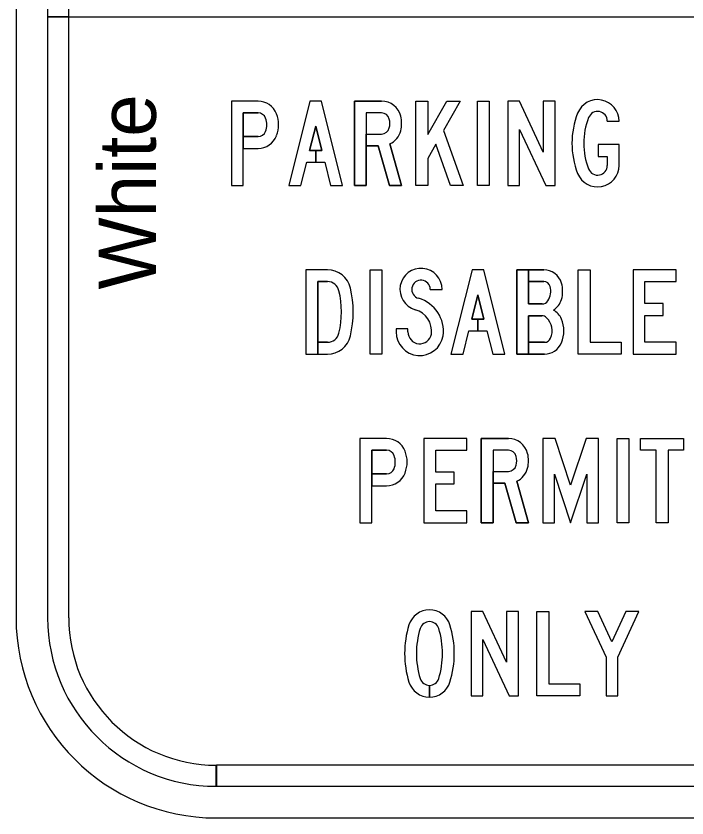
# Model space of a CAD drawing. Extents: x 0 to 770, y 0 to 495.
# Drawn here: x 274.24 to 315.4, y 369.75 to 418.91 of the extents above; entities that cross this region are included whole.
import ezdxf

# ---------------------------------------------------------------- set-up
doc = ezdxf.new("R2010")
doc.units = 0
for name, color, linetype in [('Default', 7, 'Continuous'), ('GSBWFill', 7, 'Continuous'), ('GSColorFill', 7, 'Continuous'), ('GSOutline', 7, 'Continuous'), ('TextStructures', 7, 'Continuous')]:
    doc.layers.add(name, color=color, linetype=linetype)

msp = doc.modelspace()

# ---------------------------------------------------------------- linework, layer by layer
at = {"layer": 'Default'}
for p, q in [((274.242, 450.532), (274.242, 382.027)), ((276.181, 450.532), (276.181, 418.869)), ((277.474, 418.869), (277.474, 450.532)), ((276.181, 418.869), (334.346, 418.869)), ((276.181, 418.869), (276.181, 382.027)), ((277.474, 382.027), (277.474, 418.869)), ((286.522, 371.687), (286.522, 372.979)), ((324.006, 372.979), (286.535, 372.979)), ((286.535, 372.979), (286.535, 371.687)), ((286.535, 371.687), (324.006, 371.687)), ((286.522, 369.748), (324.006, 369.748))]:
    msp.add_line(p, q, dxfattribs=at)
msp.add_lwpolyline([(277.474, 418.869), (276.181, 418.869)], dxfattribs=at)
for radius in [12.279, 10.34, 9.048]:
    msp.add_arc((286.522, 382.027), radius, 180, 270, dxfattribs=at)
at = {"layer": 'GSBWFill'}
for p, q in [((310.511, 412.466), (311.235, 412.466)), ((296.662, 411.678), (296.662, 411.678)), ((310.511, 410.308), (310.511, 409.752)), ((299.654, 402.152), (300.378, 402.152)), ((298.284, 399.541), (298.284, 399.735)), ((293.345, 398.908), (292.752, 398.908)), ((304.443, 390.997), (304.443, 390.997)), ((299.602, 377.878), (299.602, 377.154)), ((299.602, 377.154), (299.602, 377.878))]:
    msp.add_line(p, q, dxfattribs=at)
for points in [[(289.089, 413.694), (287.452, 413.694), (287.452, 408.524), (288.176, 408.524), (288.176, 412.971), (289.089, 412.971)], [(296.662, 412.971), (295.725, 412.971), (295.725, 408.524), (295.001, 408.524), (295.001, 413.694), (296.662, 413.694)], [(289.089, 411.523), (288.176, 411.523), (288.176, 410.799), (289.089, 410.799)], [(297.172, 411.066), (297.896, 408.524), (297.144, 408.524), (296.452, 410.954), (295.725, 410.954), (295.725, 411.678), (296.662, 411.678)], [(311.235, 409.752), (311.235, 411.032), (309.943, 411.032), (309.943, 410.308), (310.511, 410.308)], [(293.345, 403.354), (292.028, 403.354), (292.028, 398.184), (292.752, 398.184), (292.752, 402.63), (293.345, 402.63)], [(306.494, 400.536), (305.677, 400.536), (305.677, 398.184), (304.953, 398.184), (304.953, 403.354), (305.677, 403.354), (305.677, 401.26), (306.523, 401.26)], [(306.608, 402.63), (305.678, 402.63), (305.678, 403.354), (306.608, 403.354)], [(298.284, 399.735), (297.56, 399.735), (297.56, 399.541)], [(292.752, 398.908), (292.752, 398.184), (293.345, 398.184)], [(306.653, 398.184), (305.678, 398.184), (305.678, 398.908), (306.653, 398.908)], [(296.974, 393.014), (295.337, 393.014), (295.337, 387.843), (296.061, 387.843), (296.061, 392.29), (296.974, 392.29)], [(304.443, 392.29), (303.506, 392.29), (303.506, 387.843), (302.782, 387.843), (302.782, 393.014), (304.443, 393.014)], [(304.953, 390.386), (305.677, 387.843), (304.925, 387.843), (304.233, 390.273), (303.506, 390.273), (303.506, 390.997), (304.443, 390.997)], [(296.974, 390.842), (296.061, 390.842), (296.061, 390.118), (296.974, 390.118)]]:
    msp.add_lwpolyline(points, dxfattribs=at)
for points in [[(292.623, 410.67), (292.251, 410.67), (292.623, 412.158), (292.995, 410.67), (292.623, 410.67), (292.623, 409.946), (293.175, 409.946), (293.531, 408.524), (294.277, 408.524), (292.984, 413.694), (292.261, 413.694), (290.968, 408.524), (291.714, 408.524), (292.07, 409.946), (292.623, 409.946)], [(299.994, 411.053), (299.499, 410.179), (299.499, 408.524), (298.775, 408.524), (298.775, 413.694), (299.499, 413.694), (299.499, 411.648), (300.658, 413.694), (301.489, 413.694), (300.465, 411.885), (301.67, 408.524), (300.901, 408.524)], [(302.549, 413.694), (303.273, 413.694), (303.273, 408.524), (302.549, 408.524)], [(306.737, 408.524), (307.306, 408.524), (307.306, 413.694), (306.582, 413.694), (306.582, 410.57), (305.126, 413.694), (304.411, 413.694), (304.411, 408.524), (305.134, 408.524), (305.134, 411.962)], [(295.957, 403.354), (296.681, 403.354), (296.681, 398.184), (295.957, 398.184)], [(302.575, 400.329), (302.203, 400.329), (302.575, 401.817), (302.947, 400.329), (302.575, 400.329), (302.575, 399.606), (303.128, 399.606), (303.484, 398.184), (304.23, 398.184), (302.937, 403.354), (302.213, 403.354), (300.921, 398.184), (301.667, 398.184), (302.022, 399.606), (302.575, 399.606)], [(308.728, 403.354), (309.452, 403.354), (309.452, 398.908), (311.365, 398.908), (311.365, 398.184), (308.728, 398.184)], [(312.812, 398.908), (312.812, 400.562), (313.945, 400.562), (313.945, 401.286), (312.812, 401.286), (312.812, 402.63), (314.725, 402.63), (314.725, 403.354), (312.088, 403.354), (312.088, 398.184), (314.725, 398.184), (314.725, 398.908)], [(299.99, 388.567), (299.99, 390.222), (301.123, 390.222), (301.123, 390.946), (299.99, 390.946), (299.99, 392.29), (301.903, 392.29), (301.903, 393.014), (299.266, 393.014), (299.266, 387.843), (301.903, 387.843), (301.903, 388.567)], [(308.262, 387.843), (309.245, 390.82), (309.245, 387.843), (309.969, 387.843), (309.969, 393.014), (309.206, 393.014), (308.262, 390.153), (307.318, 393.014), (306.556, 393.014), (306.556, 387.843), (307.28, 387.843), (307.28, 390.82)], [(311.106, 393.014), (311.83, 393.014), (311.83, 387.843), (311.106, 387.843)], [(313.51, 392.29), (312.554, 392.29), (312.554, 393.014), (315.19, 393.014), (315.19, 392.29), (314.234, 392.29), (314.234, 387.843), (313.51, 387.843)], [(304.488, 377.245), (305.057, 377.245), (305.057, 382.415), (304.333, 382.415), (304.333, 379.29), (302.876, 382.415), (302.161, 382.415), (302.161, 377.245), (302.885, 377.245), (302.885, 380.683)], [(306.194, 382.415), (306.918, 382.415), (306.918, 377.968), (308.831, 377.968), (308.831, 377.245), (306.194, 377.245)], [(310.434, 379.597), (310.434, 377.245), (311.158, 377.245), (311.158, 379.597), (312.45, 382.415), (311.654, 382.415), (310.796, 380.544), (309.938, 382.415), (309.141, 382.415)]]:
    msp.add_lwpolyline(points, close=True, dxfattribs=at)
for centre, radius, start, end in [((289.089, 412.479), 1.215, 21.1002, 90), ((296.662, 412.479), 1.215, 13.8865, 90), ((309.917, 412.466), 1.318, 0, 158.4314), ((289.089, 412.479), 0.491, 21.1002, 90), ((296.662, 412.479), 0.491, 13.8865, 90), ((309.917, 412.466), 0.595, 0, 158.4314), ((288.486, 412.247), 1.137, 338.8998, 21.1002), ((288.486, 412.247), 1.861, 338.8998, 21.1002), ((296.035, 412.324), 1.137, 346.1135, 13.8865), ((296.035, 412.324), 1.861, 346.1135, 13.8865), ((313.35, 411.109), 5.01, 158.4314, 201.5686), ((313.35, 411.109), 4.286, 158.4314, 201.5686), ((296.662, 412.169), 0.491, 270, 346.1135), ((289.089, 412.014), 0.491, 270, 338.8998), ((289.089, 412.014), 1.215, 270, 338.8998), ((296.662, 412.169), 1.215, 294.8221, 346.1135), ((309.917, 409.752), 1.318, 201.5686, 0), ((309.917, 409.752), 0.595, 201.5686, 0), ((299.085, 402.152), 1.293, 0, 254.2259), ((299.085, 402.152), 0.569, 0, 254.2259), ((298.361, 399.59), 2.094, 352.1298, 74.2259), ((298.361, 399.59), 1.37, 352.5804, 74.2259), ((299.008, 399.541), 1.448, 180, 350.5313), ((299.008, 399.541), 0.724, 180, 349.7857), ((296.974, 391.799), 1.215, 21.1002, 90), ((304.443, 391.799), 1.215, 13.8865, 90), ((296.974, 391.799), 0.491, 21.1002, 90), ((296.371, 391.566), 1.137, 338.8998, 21.1002), ((296.371, 391.566), 1.861, 338.8998, 21.1002), ((304.443, 391.799), 0.491, 13.8865, 90), ((303.816, 391.644), 1.137, 346.1135, 13.8865), ((303.816, 391.644), 1.861, 346.1135, 13.8865), ((304.443, 391.488), 0.491, 270, 346.1135), ((296.974, 391.333), 0.491, 270, 338.8998), ((296.974, 391.333), 1.215, 270, 338.8998), ((304.443, 391.488), 1.215, 294.8221, 346.1135), ((299.602, 381.187), 1.318, 17.3283, 162.6717), ((303.952, 379.83), 5.875, 162.6717, 197.3283), ((299.602, 381.187), 0.595, 17.3283, 162.6717), ((295.252, 379.83), 5.875, 342.6717, 17.3283), ((303.952, 379.83), 5.151, 162.6717, 197.3283), ((295.252, 379.83), 5.151, 342.6717, 17.3283), ((299.602, 378.472), 1.318, 197.3283, 270), ((299.602, 378.472), 0.595, 197.3283, 270), ((299.602, 378.472), 0.595, 270.0249, 342.6717), ((299.602, 378.472), 1.318, 270.0112, 342.6717)]:
    msp.add_arc(centre, radius, start, end, dxfattribs=at)
for centre, major_axis, start_param, end_param in [((293.345, 401.906), (1.448, 0), 0.228795, 1.570796), ((306.608, 402.217), (0, 1.137), 4.996183, 6.283185), ((293.345, 401.906), (0.724, 0), 0.228795, 1.570796), ((288.461, 400.769), (6.463, 0), 6.05439, 6.51198), ((306.608, 402.217), (0, 0.414), 4.996183, 6.283185), ((305.988, 402.036), (0, 1.06), 4.118003, 4.996183), ((305.988, 402.036), (0, 1.784), 4.428595, 4.996183), ((288.461, 400.769), (5.739, 0), 6.05439, 6.51198), ((306.523, 401.674), (0, 0.414), 3.141593, 4.118003), ((306.608, 401.855), (0, 1.137), 3.692503, 4.428595), ((306.653, 399.89), (0, 1.137), 5.116125, 5.778288), ((306.494, 400.123), (0, 0.414), 5.507992, 6.283185), ((305.988, 399.606), (0, 1.137), 4.308652, 5.507992), ((305.988, 399.606), (0, 1.861), 4.308653, 5.116125), ((293.345, 399.631), (0.724, 0), 4.712389, 6.05439), ((293.345, 399.631), (1.448, 0), 4.712389, 6.05439), ((306.653, 399.321), (0, 0.414), 3.141593, 4.308652), ((306.653, 399.321), (0, 1.137), 3.141593, 4.308652)]:
    msp.add_ellipse(centre, major_axis=major_axis, ratio=0.999991, start_param=start_param, end_param=end_param, dxfattribs=at)
at = {"layer": 'GSColorFill'}
for p, q in [((310.511, 412.466), (311.235, 412.466)), ((296.662, 411.678), (296.662, 411.678)), ((310.511, 410.308), (310.511, 409.752)), ((299.654, 402.152), (300.378, 402.152)), ((298.284, 399.541), (298.284, 399.735)), ((293.345, 398.908), (292.752, 398.908)), ((304.443, 390.997), (304.443, 390.997)), ((299.602, 377.878), (299.602, 377.154)), ((299.602, 377.154), (299.602, 377.878))]:
    msp.add_line(p, q, dxfattribs=at)
for points in [[(289.089, 413.694), (287.452, 413.694), (287.452, 408.524), (288.176, 408.524), (288.176, 412.971), (289.089, 412.971)], [(296.662, 412.971), (295.725, 412.971), (295.725, 408.524), (295.001, 408.524), (295.001, 413.694), (296.662, 413.694)], [(289.089, 411.523), (288.176, 411.523), (288.176, 410.799), (289.089, 410.799)], [(297.172, 411.066), (297.896, 408.524), (297.144, 408.524), (296.452, 410.954), (295.725, 410.954), (295.725, 411.678), (296.662, 411.678)], [(311.235, 409.752), (311.235, 411.032), (309.943, 411.032), (309.943, 410.308), (310.511, 410.308)], [(293.345, 403.354), (292.028, 403.354), (292.028, 398.184), (292.752, 398.184), (292.752, 402.63), (293.345, 402.63)], [(306.494, 400.536), (305.677, 400.536), (305.677, 398.184), (304.953, 398.184), (304.953, 403.354), (305.677, 403.354), (305.677, 401.26), (306.523, 401.26)], [(306.608, 402.63), (305.678, 402.63), (305.678, 403.354), (306.608, 403.354)], [(298.284, 399.735), (297.56, 399.735), (297.56, 399.541)], [(292.752, 398.908), (292.752, 398.184), (293.345, 398.184)], [(306.653, 398.184), (305.678, 398.184), (305.678, 398.908), (306.653, 398.908)], [(296.974, 393.014), (295.337, 393.014), (295.337, 387.843), (296.061, 387.843), (296.061, 392.29), (296.974, 392.29)], [(304.443, 392.29), (303.506, 392.29), (303.506, 387.843), (302.782, 387.843), (302.782, 393.014), (304.443, 393.014)], [(304.953, 390.386), (305.677, 387.843), (304.925, 387.843), (304.233, 390.273), (303.506, 390.273), (303.506, 390.997), (304.443, 390.997)], [(296.974, 390.842), (296.061, 390.842), (296.061, 390.118), (296.974, 390.118)]]:
    msp.add_lwpolyline(points, dxfattribs=at)
for points in [[(292.623, 410.67), (292.251, 410.67), (292.623, 412.158), (292.995, 410.67), (292.623, 410.67), (292.623, 409.946), (293.175, 409.946), (293.531, 408.524), (294.277, 408.524), (292.984, 413.694), (292.261, 413.694), (290.968, 408.524), (291.714, 408.524), (292.07, 409.946), (292.623, 409.946)], [(299.994, 411.053), (299.499, 410.179), (299.499, 408.524), (298.775, 408.524), (298.775, 413.694), (299.499, 413.694), (299.499, 411.648), (300.658, 413.694), (301.489, 413.694), (300.465, 411.885), (301.67, 408.524), (300.901, 408.524)], [(302.549, 413.694), (303.273, 413.694), (303.273, 408.524), (302.549, 408.524)], [(306.737, 408.524), (307.306, 408.524), (307.306, 413.694), (306.582, 413.694), (306.582, 410.57), (305.126, 413.694), (304.411, 413.694), (304.411, 408.524), (305.134, 408.524), (305.134, 411.962)], [(295.957, 403.354), (296.681, 403.354), (296.681, 398.184), (295.957, 398.184)], [(302.575, 400.329), (302.203, 400.329), (302.575, 401.817), (302.947, 400.329), (302.575, 400.329), (302.575, 399.606), (303.128, 399.606), (303.484, 398.184), (304.23, 398.184), (302.937, 403.354), (302.213, 403.354), (300.921, 398.184), (301.667, 398.184), (302.022, 399.606), (302.575, 399.606)], [(308.728, 403.354), (309.452, 403.354), (309.452, 398.908), (311.365, 398.908), (311.365, 398.184), (308.728, 398.184)], [(312.812, 398.908), (312.812, 400.562), (313.945, 400.562), (313.945, 401.286), (312.812, 401.286), (312.812, 402.63), (314.725, 402.63), (314.725, 403.354), (312.088, 403.354), (312.088, 398.184), (314.725, 398.184), (314.725, 398.908)], [(299.99, 388.567), (299.99, 390.222), (301.123, 390.222), (301.123, 390.946), (299.99, 390.946), (299.99, 392.29), (301.903, 392.29), (301.903, 393.014), (299.266, 393.014), (299.266, 387.843), (301.903, 387.843), (301.903, 388.567)], [(308.262, 387.843), (309.245, 390.82), (309.245, 387.843), (309.969, 387.843), (309.969, 393.014), (309.206, 393.014), (308.262, 390.153), (307.318, 393.014), (306.556, 393.014), (306.556, 387.843), (307.28, 387.843), (307.28, 390.82)], [(311.106, 393.014), (311.83, 393.014), (311.83, 387.843), (311.106, 387.843)], [(313.51, 392.29), (312.554, 392.29), (312.554, 393.014), (315.19, 393.014), (315.19, 392.29), (314.234, 392.29), (314.234, 387.843), (313.51, 387.843)], [(304.488, 377.245), (305.057, 377.245), (305.057, 382.415), (304.333, 382.415), (304.333, 379.29), (302.876, 382.415), (302.161, 382.415), (302.161, 377.245), (302.885, 377.245), (302.885, 380.683)], [(306.194, 382.415), (306.918, 382.415), (306.918, 377.968), (308.831, 377.968), (308.831, 377.245), (306.194, 377.245)], [(310.434, 379.597), (310.434, 377.245), (311.158, 377.245), (311.158, 379.597), (312.45, 382.415), (311.654, 382.415), (310.796, 380.544), (309.938, 382.415), (309.141, 382.415)]]:
    msp.add_lwpolyline(points, close=True, dxfattribs=at)
for centre, radius, start, end in [((289.089, 412.479), 1.215, 21.1002, 90), ((296.662, 412.479), 1.215, 13.8865, 90), ((309.917, 412.466), 1.318, 0, 158.4314), ((289.089, 412.479), 0.491, 21.1002, 90), ((296.662, 412.479), 0.491, 13.8865, 90), ((309.917, 412.466), 0.595, 0, 158.4314), ((288.486, 412.247), 1.137, 338.8998, 21.1002), ((288.486, 412.247), 1.861, 338.8998, 21.1002), ((296.035, 412.324), 1.137, 346.1135, 13.8865), ((296.035, 412.324), 1.861, 346.1135, 13.8865), ((313.35, 411.109), 5.01, 158.4314, 201.5686), ((313.35, 411.109), 4.286, 158.4314, 201.5686), ((296.662, 412.169), 0.491, 270, 346.1135), ((289.089, 412.014), 0.491, 270, 338.8998), ((289.089, 412.014), 1.215, 270, 338.8998), ((296.662, 412.169), 1.215, 294.8221, 346.1135), ((309.917, 409.752), 1.318, 201.5686, 0), ((309.917, 409.752), 0.595, 201.5686, 0), ((299.085, 402.152), 1.293, 0, 254.2259), ((299.085, 402.152), 0.569, 0, 254.2259), ((298.361, 399.59), 2.094, 352.1298, 74.2259), ((298.361, 399.59), 1.37, 352.5804, 74.2259), ((299.008, 399.541), 1.448, 180, 350.5313), ((299.008, 399.541), 0.724, 180, 349.7857), ((296.974, 391.799), 1.215, 21.1002, 90), ((304.443, 391.799), 1.215, 13.8865, 90), ((296.974, 391.799), 0.491, 21.1002, 90), ((296.371, 391.566), 1.137, 338.8998, 21.1002), ((296.371, 391.566), 1.861, 338.8998, 21.1002), ((304.443, 391.799), 0.491, 13.8865, 90), ((303.816, 391.644), 1.137, 346.1135, 13.8865), ((303.816, 391.644), 1.861, 346.1135, 13.8865), ((304.443, 391.488), 0.491, 270, 346.1135), ((296.974, 391.333), 0.491, 270, 338.8998), ((296.974, 391.333), 1.215, 270, 338.8998), ((304.443, 391.488), 1.215, 294.8221, 346.1135), ((299.602, 381.187), 1.318, 17.3283, 162.6717), ((303.952, 379.83), 5.875, 162.6717, 197.3283), ((299.602, 381.187), 0.595, 17.3283, 162.6717), ((295.252, 379.83), 5.875, 342.6717, 17.3283), ((303.952, 379.83), 5.151, 162.6717, 197.3283), ((295.252, 379.83), 5.151, 342.6717, 17.3283), ((299.602, 378.472), 1.318, 197.3283, 270), ((299.602, 378.472), 0.595, 197.3283, 270), ((299.602, 378.472), 0.595, 270.0249, 342.6717), ((299.602, 378.472), 1.318, 270.0112, 342.6717)]:
    msp.add_arc(centre, radius, start, end, dxfattribs=at)
for centre, major_axis, start_param, end_param in [((293.345, 401.906), (1.448, 0), 0.228795, 1.570796), ((306.608, 402.217), (0, 1.137), 4.996183, 6.283185), ((293.345, 401.906), (0.724, 0), 0.228795, 1.570796), ((288.461, 400.769), (6.463, 0), 6.05439, 6.51198), ((306.608, 402.217), (0, 0.414), 4.996183, 6.283185), ((305.988, 402.036), (0, 1.06), 4.118003, 4.996183), ((305.988, 402.036), (0, 1.784), 4.428595, 4.996183), ((288.461, 400.769), (5.739, 0), 6.05439, 6.51198), ((306.523, 401.674), (0, 0.414), 3.141593, 4.118003), ((306.608, 401.855), (0, 1.137), 3.692503, 4.428595), ((306.653, 399.89), (0, 1.137), 5.116125, 5.778288), ((306.494, 400.123), (0, 0.414), 5.507992, 6.283185), ((305.988, 399.606), (0, 1.137), 4.308652, 5.507992), ((305.988, 399.606), (0, 1.861), 4.308653, 5.116125), ((293.345, 399.631), (0.724, 0), 4.712389, 6.05439), ((293.345, 399.631), (1.448, 0), 4.712389, 6.05439), ((306.653, 399.321), (0, 0.414), 3.141593, 4.308652), ((306.653, 399.321), (0, 1.137), 3.141593, 4.308652)]:
    msp.add_ellipse(centre, major_axis=major_axis, ratio=0.999991, start_param=start_param, end_param=end_param, dxfattribs=at)
at = {"layer": 'GSOutline'}
for p, q in [((289.089, 413.694), (287.452, 413.694)), ((296.662, 413.694), (295.001, 413.694)), ((296.662, 412.971), (296.662, 412.971)), ((310.511, 412.466), (311.235, 412.466)), ((310.511, 410.308), (310.511, 409.752)), ((299.654, 402.152), (300.378, 402.152)), ((298.284, 399.541), (298.284, 399.735)), ((292.752, 398.908), (293.345, 398.908)), ((293.345, 398.184), (293.345, 398.184)), ((296.974, 393.014), (295.337, 393.014)), ((304.443, 393.014), (302.782, 393.014)), ((304.443, 392.29), (304.443, 392.29))]:
    msp.add_line(p, q, dxfattribs=at)
for points in [[(287.452, 413.694), (287.452, 408.524), (288.176, 408.524), (288.176, 410.799), (289.089, 410.799)], [(295.001, 413.694), (295.001, 408.524), (295.725, 408.524), (295.725, 410.954), (296.452, 410.954), (297.144, 408.524), (297.896, 408.524), (297.172, 411.066)], [(289.089, 412.971), (288.176, 412.971), (288.176, 411.523), (289.089, 411.523)], [(296.662, 412.971), (295.725, 412.971), (295.725, 411.678), (296.662, 411.678)], [(311.235, 409.752), (311.235, 411.032), (309.943, 411.032), (309.943, 410.308), (310.511, 410.308)], [(293.345, 403.354), (292.028, 403.354), (292.028, 398.184), (293.345, 398.184)], [(306.608, 403.354), (304.953, 403.354), (304.953, 398.184), (306.653, 398.184)], [(293.345, 402.63), (292.752, 402.63), (292.752, 398.908)], [(306.523, 401.26), (305.677, 401.26), (305.677, 402.63), (306.608, 402.63)], [(306.653, 398.908), (305.677, 398.908), (305.677, 400.536), (306.494, 400.536)], [(298.284, 399.735), (297.56, 399.735), (297.56, 399.541)], [(295.337, 393.014), (295.337, 387.843), (296.061, 387.843), (296.061, 390.118), (296.974, 390.118)], [(302.782, 393.014), (302.782, 387.843), (303.506, 387.843), (303.506, 390.273), (304.233, 390.273), (304.925, 387.843), (305.677, 387.843), (304.953, 390.386)], [(296.974, 392.29), (296.061, 392.29), (296.061, 390.842), (296.974, 390.842)], [(304.443, 392.29), (303.506, 392.29), (303.506, 390.997), (304.443, 390.997)]]:
    msp.add_lwpolyline(points, dxfattribs=at)
for points in [[(292.07, 409.946), (293.175, 409.946), (293.531, 408.524), (294.277, 408.524), (292.984, 413.694), (292.261, 413.694), (290.968, 408.524), (291.714, 408.524)], [(299.994, 411.053), (299.499, 410.179), (299.499, 408.524), (298.775, 408.524), (298.775, 413.694), (299.499, 413.694), (299.499, 411.648), (300.658, 413.694), (301.489, 413.694), (300.465, 411.885), (301.67, 408.524), (300.901, 408.524)], [(302.549, 413.694), (303.273, 413.694), (303.273, 408.524), (302.549, 408.524)], [(306.737, 408.524), (307.306, 408.524), (307.306, 413.694), (306.582, 413.694), (306.582, 410.57), (305.126, 413.694), (304.411, 413.694), (304.411, 408.524), (305.134, 408.524), (305.134, 411.962)], [(292.995, 410.67), (292.623, 412.158), (292.251, 410.67)], [(295.957, 403.354), (296.681, 403.354), (296.681, 398.184), (295.957, 398.184)], [(302.022, 399.606), (303.128, 399.606), (303.484, 398.184), (304.23, 398.184), (302.937, 403.354), (302.213, 403.354), (300.921, 398.184), (301.667, 398.184)], [(308.728, 403.354), (309.452, 403.354), (309.452, 398.908), (311.365, 398.908), (311.365, 398.184), (308.728, 398.184)], [(312.812, 398.908), (312.812, 400.562), (313.945, 400.562), (313.945, 401.286), (312.812, 401.286), (312.812, 402.63), (314.725, 402.63), (314.725, 403.354), (312.088, 403.354), (312.088, 398.184), (314.725, 398.184), (314.725, 398.908)], [(302.947, 400.329), (302.575, 401.817), (302.203, 400.329)], [(299.99, 388.567), (299.99, 390.222), (301.123, 390.222), (301.123, 390.946), (299.99, 390.946), (299.99, 392.29), (301.903, 392.29), (301.903, 393.014), (299.266, 393.014), (299.266, 387.843), (301.903, 387.843), (301.903, 388.567)], [(308.262, 387.843), (309.245, 390.82), (309.245, 387.843), (309.969, 387.843), (309.969, 393.014), (309.206, 393.014), (308.262, 390.153), (307.318, 393.014), (306.556, 393.014), (306.556, 387.843), (307.28, 387.843), (307.28, 390.82)], [(311.106, 393.014), (311.83, 393.014), (311.83, 387.843), (311.106, 387.843)], [(313.51, 392.29), (312.554, 392.29), (312.554, 393.014), (315.19, 393.014), (315.19, 392.29), (314.234, 392.29), (314.234, 387.843), (313.51, 387.843)], [(304.488, 377.245), (305.057, 377.245), (305.057, 382.415), (304.333, 382.415), (304.333, 379.29), (302.876, 382.415), (302.161, 382.415), (302.161, 377.245), (302.885, 377.245), (302.885, 380.683)], [(306.194, 382.415), (306.918, 382.415), (306.918, 377.968), (308.831, 377.968), (308.831, 377.245), (306.194, 377.245)], [(310.434, 379.597), (310.434, 377.245), (311.158, 377.245), (311.158, 379.597), (312.45, 382.415), (311.654, 382.415), (310.796, 380.544), (309.938, 382.415), (309.141, 382.415)]]:
    msp.add_lwpolyline(points, close=True, dxfattribs=at)
for centre, radius, start, end in [((289.089, 412.479), 1.215, 21.1002, 90), ((296.662, 412.479), 1.215, 13.8865, 90), ((309.917, 412.466), 1.318, 0, 158.4314), ((289.089, 412.479), 0.491, 21.1002, 90), ((296.662, 412.479), 0.491, 13.8865, 90), ((309.917, 412.466), 0.595, 0, 158.4314), ((288.486, 412.247), 1.137, 338.8998, 21.1002), ((288.486, 412.247), 1.861, 338.8998, 21.1002), ((296.035, 412.324), 1.137, 346.1135, 13.8865), ((296.035, 412.324), 1.861, 346.1135, 13.8865), ((313.35, 411.109), 5.01, 158.4314, 201.5686), ((313.35, 411.109), 4.286, 158.4314, 201.5686), ((296.662, 412.169), 0.491, 270, 346.1135), ((289.089, 412.014), 0.491, 270, 338.8998), ((289.089, 412.014), 1.215, 270, 338.8998), ((296.662, 412.169), 1.215, 294.8221, 346.1135), ((309.917, 409.752), 1.318, 201.5686, 0), ((309.917, 409.752), 0.595, 201.5686, 0), ((299.085, 402.152), 1.293, 0, 254.2259), ((299.085, 402.152), 0.569, 0, 254.2259), ((298.361, 399.59), 2.094, 352.1298, 74.2259), ((298.361, 399.59), 1.37, 352.5804, 74.2259), ((299.008, 399.541), 1.448, 180, 350.5313), ((299.008, 399.541), 0.724, 180, 349.7857), ((296.974, 391.799), 1.215, 21.1002, 90), ((304.443, 391.799), 1.215, 13.8865, 90), ((296.974, 391.799), 0.491, 21.1002, 90), ((296.371, 391.566), 1.137, 338.8998, 21.1002), ((296.371, 391.566), 1.861, 338.8998, 21.1002), ((304.443, 391.799), 0.491, 13.8865, 90), ((303.816, 391.644), 1.137, 346.1135, 13.8865), ((303.816, 391.644), 1.861, 346.1135, 13.8865), ((304.443, 391.488), 0.491, 270, 346.1135), ((296.974, 391.333), 0.491, 270, 338.8998), ((296.974, 391.333), 1.215, 270, 338.8998), ((304.443, 391.488), 1.215, 294.8221, 346.1135), ((299.602, 381.187), 1.318, 17.3283, 162.6717), ((303.952, 379.83), 5.875, 162.6717, 197.3283), ((299.602, 381.187), 0.595, 17.3283, 162.6717), ((295.252, 379.83), 5.875, 342.6717, 17.3283), ((303.952, 379.83), 5.151, 162.6717, 197.3283), ((295.252, 379.83), 5.151, 342.6717, 17.3283), ((299.602, 378.472), 1.318, 197.3283, 342.6717), ((299.602, 378.472), 0.595, 197.3283, 342.6717)]:
    msp.add_arc(centre, radius, start, end, dxfattribs=at)
for centre, major_axis, start_param, end_param in [((293.345, 401.906), (1.448, 0), 0.228795, 1.570796), ((306.608, 402.217), (0, 1.137), 4.996183, 6.283185), ((293.345, 401.906), (0.724, 0), 0.228795, 1.570796), ((288.461, 400.769), (6.463, 0), 6.05439, 6.51198), ((306.608, 402.217), (0, 0.414), 4.996183, 6.283185), ((305.988, 402.036), (0, 1.06), 4.118003, 4.996183), ((305.988, 402.036), (0, 1.784), 4.428595, 4.996183), ((288.461, 400.769), (5.739, 0), 6.05439, 6.51198), ((306.523, 401.674), (0, 0.414), 3.141593, 4.118003), ((306.608, 401.855), (0, 1.137), 3.692503, 4.428595), ((306.653, 399.89), (0, 1.137), 5.116125, 5.778288), ((306.494, 400.123), (0, 0.414), 5.507992, 6.283185), ((305.988, 399.606), (0, 1.137), 4.308652, 5.507992), ((305.988, 399.606), (0, 1.861), 4.308652, 5.116125), ((293.345, 399.631), (0.724, 0), 4.712389, 6.05439), ((293.345, 399.631), (1.448, 0), 4.712389, 6.05439), ((306.653, 399.321), (0, 0.414), 3.141593, 4.308652), ((306.653, 399.321), (0, 1.137), 3.141593, 4.308652)]:
    msp.add_ellipse(centre, major_axis=major_axis, ratio=0.999991, start_param=start_param, end_param=end_param, dxfattribs=at)

# ---------------------------------------------------------------- texts
at = {"layer": 'TextStructures'}
msp.add_text('White', height=3.5, rotation=90, dxfattribs=at).set_placement((282.82, 402.149))

doc.saveas('drawing.dxf')
